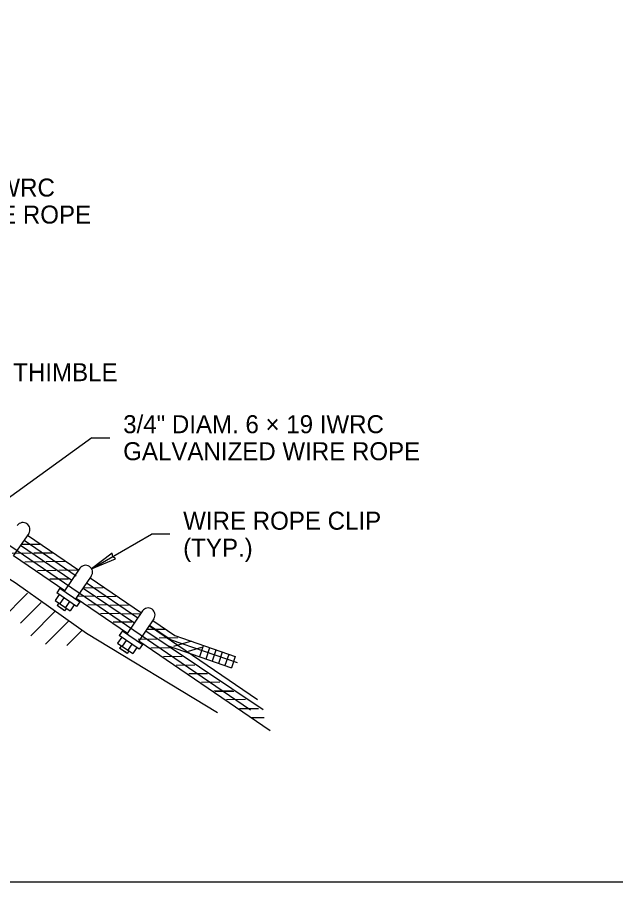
# Model space of a CAD drawing. Extents: x 99861 to 103151, y 100000 to 102076.
# Drawn here: x 100810 to 101342, y 100000 to 100768 of the extents above; entities that cross this region are included whole.
import ezdxf

# ---------------------------------------------------------------- set-up
doc = ezdxf.new("R2010")
doc.units = 0
for name, color, linetype in [('Level 1', 7, 'Continuous'), ('Level 10', 7, 'Continuous'), ('Level 15', 7, 'Continuous'), ('Level 2', 7, 'Continuous'), ('Level 20', 7, 'Continuous'), ('Level 28', 7, 'Continuous'), ('Level 4', 7, 'Continuous')]:
    doc.layers.add(name, color=color, linetype=linetype)

msp = doc.modelspace()

# ---------------------------------------------------------------- linework, layer by layer
at = {"layer": 'Level 1'}
for p, q in [((100819.5, 100308.09), (100865.04, 100277.01)), ((100813.3, 100299.01), (100858.77, 100267.98)), ((100807.1, 100289.92), (100852.57, 100258.89)), ((100875.21, 100270.08), (100920.67, 100239.06)), ((100868.94, 100261.04), (100914.4, 100230.02)), ((100862.74, 100251.95), (100908.2, 100220.93)), ((100918.37, 100213.99), (101035.08, 100134.35)), ((100944.43, 100209.53), (101028.96, 100153.06)), ((101003.91, 100200.12), (101000.55, 100190.23))]:
    msp.add_line(p, q, dxfattribs=at)
msp.add_lwpolyline([(99861, 100000), (103150, 100000), (103150, 102076), (99861, 102076)], close=True, dxfattribs=at)
for points in [[(100930.84, 100232.12), (100950.3, 100218.84), (101003.91, 100200.12)], [(100924.57, 100223.08), (100944.43, 100209.53), (101000.55, 100190.23)]]:
    msp.add_lwpolyline(points, dxfattribs=at)
at = {"layer": 'Level 10'}
for p, q in [((100795.86, 100232.8), (100819.39, 100256.34)), ((100813.21, 100229.78), (100831.61, 100248.19)), ((100822.3, 100218.51), (100843.83, 100240.04)), ((100822.3, 100218.51), (100843.83, 100240.04)), ((100835.33, 100211.18), (100856.05, 100231.9)), ((100854.4, 100209.89), (100868.27, 100223.75)), ((100880.09, 100215.21), (100880.49, 100215.61)), ((100880.09, 100215.21), (100880.49, 100215.61))]:
    msp.add_line(p, q, dxfattribs=at)
at = {"layer": 'Level 15'}
for p, q in [((100876.45, 100394.66), (100786.62, 100329.56)), ((100876.45, 100394.66), (100892.45, 100394.66)), ((100876.42, 100278.1), (100929.75, 100308.89)), ((100945.75, 100308.89), (100929.75, 100308.89))]:
    msp.add_line(p, q, dxfattribs=at)
msp.add_lwpolyline([(100876.42, 100278.1), (100897.68, 100286.92), (100895.28, 100288.98), (100894.7, 100292.1)], close=True, dxfattribs=at)
at = {"layer": 'Level 2'}
msp.add_lwpolyline([(100549.91, 100457.1), (100654.66, 100368.29), (100709.41, 100337.34), (100740.32, 100314.17), (100760.67, 100302.17), (100798.98, 100271.91), (100808.43, 100266.08), (100871.82, 100220.81), (100988.21, 100150.42)], dxfattribs=at)
at = {"layer": 'Level 28'}
for p, q in [((100820.5, 100309.64), (100806.78, 100289.57)), ((100865.94, 100278.61), (100852.23, 100258.54)), ((100876.1, 100271.66), (100862.39, 100251.6)), ((100863, 100244.69), (100845.38, 100256.74)), ((100848.27, 100260.97), (100865.87, 100248.9)), ((100847.22, 100247.79), (100845.63, 100245.47)), ((100851.57, 100252.37), (100848.05, 100247.22)), ((100856.65, 100249.04), (100853.06, 100243.79)), ((100852.41, 100240.84), (100845.63, 100245.47)), ((100851.34, 100241.57), (100847.16, 100244.43)), ((100853.99, 100243.16), (100852.41, 100240.84)), ((100860.88, 100246.14), (100857.3, 100240.9)), ((100921.55, 100240.63), (100907.83, 100220.57)), ((100931.71, 100233.69), (100918, 100213.62)), ((100918.6, 100206.72), (100900.99, 100218.76)), ((100903.88, 100222.99), (100921.48, 100210.93)), ((100902.83, 100209.81), (100901.24, 100207.5)), ((100907.18, 100214.4), (100903.66, 100209.24)), ((100912.25, 100211.06), (100908.67, 100205.82)), ((100916.49, 100208.17), (100912.9, 100202.92)), ((100908.02, 100202.87), (100901.24, 100207.5)), ((100906.95, 100203.6), (100902.76, 100206.46)), ((100909.6, 100205.18), (100908.02, 100202.87))]:
    msp.add_line(p, q, dxfattribs=at)
for points in [[(100847.5, 100255.29), (100843.91, 100250.05), (100857.3, 100240.9)], [(100848.27, 100260.97), (100845.38, 100256.74)], [(100865.87, 100248.9), (100863, 100244.69)], [(100903.11, 100217.31), (100899.52, 100212.07), (100912.9, 100202.92)], [(100903.88, 100222.99), (100900.99, 100218.76)], [(100921.48, 100210.93), (100918.6, 100206.72)]]:
    msp.add_lwpolyline(points, dxfattribs=at)
for centre in [(100815.42, 100313.11), (100871.02, 100275.14), (100926.63, 100237.16)]:
    msp.add_arc(centre, 6.15, 325.64772, 145.64772, dxfattribs=at)
at = {"layer": 'Level 4'}
for p, q in [((100797.21, 100303.33), (101017.69, 100152.88)), ((100816.4, 100303.55), (100862.68, 100271.97)), ((100830.29, 100299.82), (100813.72, 100299.62)), ((100822.3, 100291.96), (100805.74, 100291.76)), ((100841.5, 100292.17), (100824.93, 100291.97)), ((100833.51, 100284.31), (100816.95, 100284.11)), ((100852.71, 100284.52), (100836.14, 100284.33)), ((100844.72, 100276.66), (100828.16, 100276.46)), ((100863.92, 100276.88), (100847.35, 100276.68)), ((100855.93, 100269.01), (100839.37, 100268.81)), ((100871.48, 100265.96), (100917.57, 100234.51)), ((100870.05, 100261.19), (100886.62, 100261.39)), ((100870.05, 100261.19), (100886.62, 100261.39)), ((100878.35, 100253.71), (100863.71, 100253.53)), ((100881.26, 100253.54), (100897.83, 100253.74)), ((100881.26, 100253.54), (100897.83, 100253.74)), ((100889.56, 100246.06), (100873, 100245.86)), ((100892.47, 100245.89), (100909.04, 100246.09)), ((100892.47, 100245.89), (100909.04, 100246.09)), ((100900.77, 100238.41), (100884.21, 100238.21)), ((100903.68, 100238.24), (100920.25, 100238.44)), ((100903.68, 100238.24), (100920.25, 100238.44)), ((100911.98, 100230.76), (100895.42, 100230.56)), ((100941.84, 100224.31), (100925.27, 100224.11)), ((100927.74, 100227.58), (101023.83, 100162)), ((100953.05, 100216.66), (100936.48, 100216.46)), ((100934.4, 100215.46), (100917.84, 100215.26)), ((100965.21, 100213.75), (100949.29, 100209.18)), ((100973.91, 100208.15), (100962.12, 100204.76)), ((100975.5, 100209.76), (100972.14, 100199.87)), ((100945.61, 100207.81), (100929.05, 100207.61)), ((100981.18, 100207.84), (100977.82, 100197.94)), ((100986.86, 100205.91), (100983.5, 100196.01)), ((100992.54, 100203.98), (100989.19, 100194.09)), ((100998.23, 100202.05), (100994.87, 100192.16)), ((100956.82, 100200.16), (100940.26, 100199.96)), ((100968.03, 100192.52), (100951.47, 100192.32)), ((100979.24, 100184.87), (100962.68, 100184.67)), ((100990.45, 100177.22), (100973.89, 100177.02)), ((101001.66, 100169.57), (100985.09, 100169.37)), ((101002.79, 100169.09), (100986.17, 100168.89)), ((101013.2, 100161.92), (100996.3, 100161.72)), ((101024.69, 100153.75), (101007.8, 100153.54)), ((101029.84, 100145.81), (101018.02, 100145.67))]:
    msp.add_line(p, q, dxfattribs=at)
msp.add_lwpolyline([(100927.95, 100228.04), (100947.14, 100214.94), (101005.73, 100194.79)], dxfattribs=at)

# ---------------------------------------------------------------- texts
at = {"layer": 'Level 20'}
for s, p in [('3/4" DIAM. 6 × 19 IWRC', (100612, 100609)), ('GALVANIZED WIRE ROPE', (100612, 100585)), ('THIMBLE', (100806.74, 100444.9)), ('3/4" DIAM. 6 × 19 IWRC', (100904.45, 100398.66)), ('GALVANIZED WIRE ROPE', (100904.45, 100374.66)), ('WIRE ROPE CLIP ', (100957.75, 100312.89)), ('(TYP.)', (100957.75, 100288.89))]:
    msp.add_text(s, height=16, dxfattribs=at).set_placement(p)

doc.saveas('drawing.dxf')
